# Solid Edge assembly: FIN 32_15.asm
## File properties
Title: Zylinder
Author: bmolnar
Template: iso assembly.asm
Last saved by: bmolnar
Revision: 8
Application: Solid Edge
Username: bmolnar
Dokumentum tartalom típus: 1
Document Number: FIN 32/15
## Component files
Kolbenstange.par
Profilrohr.par
Kit_1.par
Kit_2.par
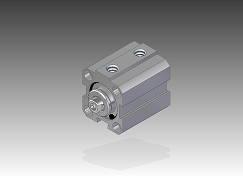
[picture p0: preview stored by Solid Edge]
